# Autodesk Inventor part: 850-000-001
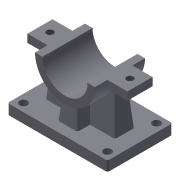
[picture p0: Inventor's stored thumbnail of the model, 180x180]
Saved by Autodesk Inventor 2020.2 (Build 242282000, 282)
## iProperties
Created: 2005-02
Part Number: 850-000-001
Document SubType Name: Modeling
Designer: F.Stasiak
Manufacturer: Standard
Standards Organization: Custom
Description: Podpora
Authority: B.S.
Material: St1203
Mass: 1118.62 g
Surface Area: 322.623 cm^2
Volume: 142.499 cm^3
Density: 7.85 g/cm^3
Appearance: Metal-Stal
Manager: www.cadconsulting.pl
Company: Fabian Stasiak CAD Consulting
Author: F.Stasiak
Subject: Zbiór ćwiczeń. Autodesk Inventor 2020. Kurs podstawowy
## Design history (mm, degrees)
sketch "Szkic1"
  geometry: L1 (-50, 32.5)-(50, 32.5); L2 (50, 32.5)-(50, -32.5); L3 (50, -32.5)-(-50, -32.5); L4 (-50, -32.5)-(-50, 32.5); L5 (0, 32.5)-(0, -32.5); 2 further points
  constraints: 10 end point, 3 midpoint, 2 parallel, 1 coincident, 1 horizontal, 1 perpendicular
  dimensions: "d0" = 100 distance of L2.end L3.end; "d106" = 65 distance of L1.end L2.end
extrude "Wyciągnięcie proste1" new body sketch "Szkic1" distance "d2" = 10; taper "d3" = 0 deg
sketch "Szkic2"
  geometry: L1 (50, 32.5)-(50, -32.5); L2 (-50, 32.5)-(50, 32.5) reference; L3 (-50, -32.5)-(-50, 32.5) reference; L4 (50, -32.5)-(-50, -32.5) reference; L5 (-35, 10)-(35, 10); L6 (35, 10)-(35, -10); L7 (35, -10)-(-35, -10); L8 (-35, -10)-(-35, 10); 4 further points
  constraints: 10 end point, 4 midpoint, 4 parallel, 1 horizontal alignment, 1 vertical alignment
  dimensions: "d4" = 20 distance of L5.end L6.end; "d118" = 70 distance of L5.start L5.end
extrude "Wyciągnięcie proste2" join sketch "Szkic2" distance "d5" = 50; taper "d6" = -5 deg
sketch "Szkic3"
  geometry: L1 (30.626, 60)-(-30.626, 60) reference; A1 r 30 centre (0, 60) between (-30, 60) and (30, 60)
  constraints: 2 end point, 2 point on circle, 2 point on line, 1 centre point, 1 midpoint
  dimensions: "d119" = 60 diameter of A1
extrude "Wyciągnięcie proste3" join sketch "Szkic3" stored distance "d7" = 50; taper "d8" = 0 deg
sketch "Szkic4"
  geometry: C1 r 22.5 at (0, 60)
  constraints: 1 centre point
  dimensions: "d9" = 45 diameter of C1
extrude "Wyciągnięcie proste4" cut sketch "Szkic4" extent not by distance; stored distance "d10" = 10; taper "d11" = 0 deg
sketch "Szkic5"
  geometry: L1 (50, -32.5)-(-50, -32.5); L2 (-10, 22.5)-(10, 22.5) reference; L3 (10, 22.5)-(10, -22.5) reference; L4 (10, -22.5)-(-10, -22.5) reference; L5 (-10, -22.5)-(-10, 22.5) reference; L6 (50, 32.5)-(50, -32.5) reference; 2 further points
  constraints: 10 end point, 3 horizontal, 2 midpoint, 2 parallel, 2 vertical, 1 horizontal alignment, 1 perpendicular
extrude "Wyciągnięcie proste5" join sketch "Szkic5" stored distance "d14" = 10; taper "d15" = -5 deg
sketch "Szkic10"
  geometry: L1 (60, 45)-(52, 45) reference; L2 (60, 20)-(60, 45) reference; L3 (52, 20)-(60, 20) reference; L4 (52, 45)-(52, 20) reference
extrude "Wyciągnięcie proste10" join sketch "Szkic10" stored distance "d31" = 10; taper "d32" = 0 deg
hole "Otwór3" diameter "d51" = 8; stored, may be unused: countersink angle "d55" = 90 deg, drill point angle "d57" = 118 deg; dims "d49" = 8, "d50" = 8, "d52" = 6, "d53" = 4, "d54" = 2, "d56" = 8
hole "Otwór4" diameter "d60" = 8; stored, may be unused: countersink angle "d64" = 90 deg, drill point angle "d66" = 118 deg; dims "d58" = 8, "d59" = 8, "d61" = 6, "d62" = 4, "d63" = 2, "d65" = 8
hole "Otwór5" diameter "d69" = 8; stored, may be unused: countersink angle "d73" = 90 deg, drill point angle "d75" = 118 deg; dims "d67" = 8, "d68" = 8, "d70" = 6, "d71" = 4, "d72" = 2, "d74" = 8
hole "Otwór6" diameter "d78" = 8; stored, may be unused: countersink angle "d82" = 90 deg, drill point angle "d84" = 118 deg; dims "d76" = 8, "d77" = 8, "d79" = 6, "d80" = 4, "d81" = 2, "d83" = 8
sketch "Szkic13"
  geometry: L1 (-50, 12.5)-(-50, -12.5) reference; L2 (-50, -12.5)-(-30, -12.5) reference; 4 further points
  constraints: 2 midpoint, 1 horizontal alignment, 1 vertical alignment
hole "Otwór10" sketch "Szkic13" at (-40, 0) diameter "d120" = 6.647; stored, may be unused: countersink angle "d124" = 90 deg, drill point angle "d126" = 118 deg; dims "d121" = 16, "d122" = 4, "d123" = 2, "d125" = 22.2
mirror "Odbicie lustrzane1"
fillet "Zaokrąglenie7" dims "d114" = 2
fillet "Zaokrąglenie8" dims "d116" = 2
node "Bryła1"
node "Korpusy bryłowe"
node "Korpusy powierzchniowe"
